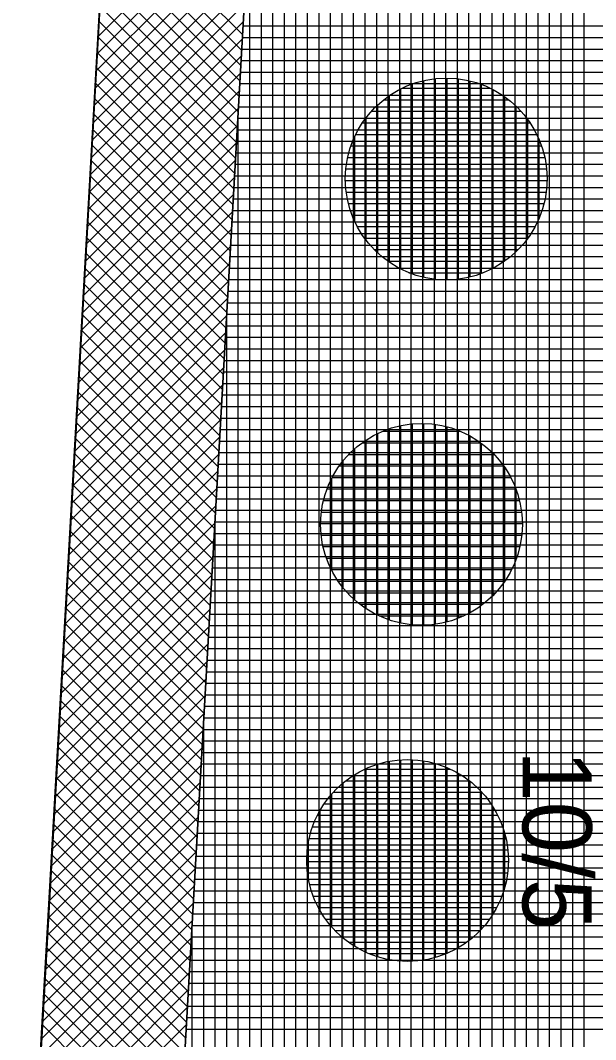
# Model space of a CAD drawing. Extents: x -565346 to -564154, y -1097386 to -1095620.
# Drawn here: x -564266.37 to -564256.39, y -1096598.57 to -1096580.89 of the extents above; entities that cross this region are included whole.
import ezdxf

# ---------------------------------------------------------------- set-up
doc = ezdxf.new("R2010")
doc.units = 0
for name, color, linetype in [('Vrstva 1', 7, 'Continuous'), ('Vrstva 40', 7, 'Continuous'), ('Vrstva 41', 7, 'Continuous'), ('Vrstva 42', 7, 'Continuous'), ('Vrstva 43', 7, 'Continuous'), ('Vrstva 44', 7, 'Continuous')]:
    doc.layers.add(name, color=color, linetype=linetype)

msp = doc.modelspace()

# ---------------------------------------------------------------- linework, layer by layer
at = {"layer": 'Vrstva 1'}
msp.add_line((-564275.31, -1096762.41), (-564264.72, -1096575.85), dxfattribs=at)
at = {"layer": 'Vrstva 41'}
msp.add_lwpolyline([(-564230.6, -1096442.93), (-564234.67, -1096447.65), (-564259.14, -1096527.84), (-564264.72, -1096575.85), (-564272.07, -1096706.16), (-564269.623, -1096706.334), (-564262.228, -1096576.061), (-564256.683, -1096528.354)], close=True, dxfattribs=at)
at = {"layer": 'Vrstva 42'}
for p, q in [((-564262.367, -1096578.518), (-564265.02, -1096581.171)), ((-564264.885, -1096578.772), (-564262.516, -1096581.141)), ((-564262.385, -1096578.818), (-564265.037, -1096581.471)), ((-564262.402, -1096579.118), (-564265.054, -1096581.77)), ((-564264.9, -1096579.04), (-564262.532, -1096581.408)), ((-564264.915, -1096579.308), (-564262.547, -1096581.676)), ((-564262.419, -1096579.418), (-564265.071, -1096582.07)), ((-564264.93, -1096579.575), (-564262.562, -1096581.944)), ((-564262.436, -1096579.718), (-564265.088, -1096582.37)), ((-564264.945, -1096579.843), (-564262.577, -1096582.211)), ((-564262.453, -1096580.018), (-564265.105, -1096582.67)), ((-564264.96, -1096580.111), (-564262.592, -1096582.479)), ((-564262.47, -1096580.317), (-564265.122, -1096582.969)), ((-564264.975, -1096580.379), (-564262.608, -1096582.747)), ((-564262.487, -1096580.617), (-564265.138, -1096583.269)), ((-564264.991, -1096580.646), (-564262.623, -1096583.014)), ((-564262.504, -1096580.917), (-564265.155, -1096583.569)), ((-564265.006, -1096580.914), (-564262.638, -1096583.282)), ((-564262.521, -1096581.217), (-564265.172, -1096583.869)), ((-564265.021, -1096581.182), (-564262.653, -1096583.549)), ((-564262.538, -1096581.517), (-564265.189, -1096584.168)), ((-564265.036, -1096581.45), (-564262.668, -1096583.817)), ((-564265.051, -1096581.717), (-564262.683, -1096584.085)), ((-564262.555, -1096581.817), (-564265.206, -1096584.468)), ((-564262.572, -1096582.117), (-564265.223, -1096584.768)), ((-564265.066, -1096581.985), (-564262.699, -1096584.352)), ((-564265.081, -1096582.253), (-564262.714, -1096584.62)), ((-564262.589, -1096582.417), (-564265.24, -1096585.068)), ((-564265.096, -1096582.521), (-564262.729, -1096584.888)), ((-564262.606, -1096582.716), (-564265.257, -1096585.367)), ((-564265.111, -1096582.788), (-564262.744, -1096585.155)), ((-564262.623, -1096583.016), (-564265.274, -1096585.667)), ((-564265.126, -1096583.056), (-564262.759, -1096585.423)), ((-564262.64, -1096583.316), (-564265.291, -1096585.967)), ((-564265.142, -1096583.324), (-564262.775, -1096585.691)), ((-564262.657, -1096583.616), (-564265.308, -1096586.267)), ((-564265.157, -1096583.591), (-564262.79, -1096585.958)), ((-564265.172, -1096583.859), (-564262.805, -1096586.226)), ((-564262.674, -1096583.916), (-564265.324, -1096586.566)), ((-564262.691, -1096584.216), (-564265.341, -1096586.866)), ((-564265.187, -1096584.127), (-564262.82, -1096586.494)), ((-564265.202, -1096584.395), (-564262.835, -1096586.761)), ((-564262.708, -1096584.516), (-564265.358, -1096587.166)), ((-564265.217, -1096584.662), (-564262.851, -1096587.029)), ((-564262.725, -1096584.815), (-564265.375, -1096587.466)), ((-564265.232, -1096584.93), (-564262.866, -1096587.297)), ((-564262.742, -1096585.115), (-564265.392, -1096587.765)), ((-564265.247, -1096585.198), (-564262.881, -1096587.564)), ((-564262.759, -1096585.415), (-564265.409, -1096588.065)), ((-564265.262, -1096585.466), (-564262.896, -1096587.832)), ((-564262.776, -1096585.715), (-564265.426, -1096588.365)), ((-564265.277, -1096585.733), (-564262.911, -1096588.1)), ((-564262.793, -1096586.015), (-564265.443, -1096588.665)), ((-564265.293, -1096586.001), (-564262.927, -1096588.367)), ((-564262.81, -1096586.315), (-564265.46, -1096588.964)), ((-564265.308, -1096586.269), (-564262.942, -1096588.635)), ((-564265.323, -1096586.537), (-564262.957, -1096588.902)), ((-564262.827, -1096586.615), (-564265.477, -1096589.264)), ((-564262.844, -1096586.914), (-564265.494, -1096589.564)), ((-564265.338, -1096586.804), (-564262.972, -1096589.17)), ((-564265.353, -1096587.072), (-564262.987, -1096589.438)), ((-564262.861, -1096587.214), (-564265.51, -1096589.864)), ((-564265.368, -1096587.34), (-564263.003, -1096589.705)), ((-564262.878, -1096587.514), (-564265.527, -1096590.163)), ((-564265.383, -1096587.608), (-564263.018, -1096589.973)), ((-564262.895, -1096587.814), (-564265.544, -1096590.463)), ((-564265.398, -1096587.875), (-564263.033, -1096590.241)), ((-564262.912, -1096588.114), (-564265.561, -1096590.763)), ((-564265.413, -1096588.143), (-564263.048, -1096590.508)), ((-564262.929, -1096588.414), (-564265.578, -1096591.063)), ((-564265.428, -1096588.411), (-564263.063, -1096590.776)), ((-564265.444, -1096588.679), (-564263.078, -1096591.044)), ((-564262.946, -1096588.714), (-564265.595, -1096591.362)), ((-564262.963, -1096589.014), (-564265.612, -1096591.662)), ((-564265.459, -1096588.946), (-564263.094, -1096591.311)), ((-564265.474, -1096589.214), (-564263.109, -1096591.579)), ((-564262.98, -1096589.313), (-564265.629, -1096591.962)), ((-564265.489, -1096589.482), (-564263.124, -1096591.847)), ((-564262.997, -1096589.613), (-564265.646, -1096592.262)), ((-564263.014, -1096589.913), (-564265.663, -1096592.561)), ((-564265.504, -1096589.75), (-564263.139, -1096592.114)), ((-564265.519, -1096590.017), (-564263.154, -1096592.382)), ((-564263.031, -1096590.213), (-564265.679, -1096592.861)), ((-564265.534, -1096590.285), (-564263.17, -1096592.65)), ((-564263.048, -1096590.513), (-564265.696, -1096593.161)), ((-564265.549, -1096590.553), (-564263.185, -1096592.917)), ((-564263.065, -1096590.813), (-564265.713, -1096593.461)), ((-564265.564, -1096590.82), (-564263.2, -1096593.185)), ((-564263.082, -1096591.113), (-564265.73, -1096593.76)), ((-564265.579, -1096591.088), (-564263.215, -1096593.453)), ((-564263.099, -1096591.412), (-564265.747, -1096594.06)), ((-564265.595, -1096591.356), (-564263.23, -1096593.72)), ((-564265.61, -1096591.624), (-564263.246, -1096593.988)), ((-564263.116, -1096591.712), (-564265.764, -1096594.36)), ((-564263.133, -1096592.012), (-564265.781, -1096594.66)), ((-564265.625, -1096591.891), (-564263.261, -1096594.255)), ((-564265.64, -1096592.159), (-564263.276, -1096594.523)), ((-564263.15, -1096592.312), (-564265.798, -1096594.959)), ((-564265.655, -1096592.427), (-564263.291, -1096594.791)), ((-564263.168, -1096592.612), (-564265.815, -1096595.259)), ((-564265.67, -1096592.695), (-564263.306, -1096595.058)), ((-564263.185, -1096592.912), (-564265.832, -1096595.559)), ((-564265.685, -1096592.962), (-564263.322, -1096595.326)), ((-564263.202, -1096593.212), (-564265.849, -1096595.859)), ((-564265.7, -1096593.23), (-564263.337, -1096595.594)), ((-564263.219, -1096593.511), (-564265.865, -1096596.158)), ((-564265.715, -1096593.498), (-564263.352, -1096595.861)), ((-564265.731, -1096593.766), (-564263.367, -1096596.129)), ((-564263.236, -1096593.811), (-564265.882, -1096596.458)), ((-564263.253, -1096594.111), (-564265.899, -1096596.758)), ((-564265.746, -1096594.033), (-564263.382, -1096596.397)), ((-564265.761, -1096594.301), (-564263.398, -1096596.664)), ((-564263.27, -1096594.411), (-564265.916, -1096597.058)), ((-564265.776, -1096594.569), (-564263.413, -1096596.932)), ((-564263.287, -1096594.711), (-564265.933, -1096597.357)), ((-564265.791, -1096594.837), (-564263.428, -1096597.2)), ((-564263.304, -1096595.011), (-564265.95, -1096597.657)), ((-564265.806, -1096595.104), (-564263.443, -1096597.467)), ((-564263.321, -1096595.311), (-564265.967, -1096597.957)), ((-564265.821, -1096595.372), (-564263.458, -1096597.735)), ((-564263.338, -1096595.611), (-564265.984, -1096598.257)), ((-564265.836, -1096595.64), (-564263.474, -1096598.003)), ((-564263.355, -1096595.91), (-564266.001, -1096598.556)), ((-564265.851, -1096595.908), (-564263.489, -1096598.27)), ((-564263.372, -1096596.21), (-564266.018, -1096598.856)), ((-564265.866, -1096596.175), (-564263.504, -1096598.538)), ((-564265.882, -1096596.443), (-564263.519, -1096598.805)), ((-564263.389, -1096596.51), (-564266.035, -1096599.156)), ((-564263.406, -1096596.81), (-564266.051, -1096599.456)), ((-564265.897, -1096596.711), (-564263.534, -1096599.073)), ((-564265.912, -1096596.979), (-564263.549, -1096599.341)), ((-564263.423, -1096597.11), (-564266.068, -1096599.755)), ((-564265.927, -1096597.246), (-564263.565, -1096599.608)), ((-564263.44, -1096597.41), (-564266.085, -1096600.055)), ((-564265.942, -1096597.514), (-564263.58, -1096599.876)), ((-564263.457, -1096597.71), (-564266.102, -1096600.355)), ((-564265.957, -1096597.782), (-564263.595, -1096600.144)), ((-564263.474, -1096598.009), (-564266.119, -1096600.655)), ((-564265.972, -1096598.05), (-564263.61, -1096600.411)), ((-564263.491, -1096598.309), (-564266.136, -1096600.954)), ((-564265.987, -1096598.317), (-564263.625, -1096600.679))]:
    msp.add_line(p, q, dxfattribs=at)
at = {"layer": 'Vrstva 43'}
for p, q in [((-564256.59, -1096609.053), (-564256.59, -1096528.049)), ((-564256.79, -1096612.576), (-564256.79, -1096529.275)), ((-564256.99, -1096616.099), (-564256.99, -1096530.995)), ((-564257.19, -1096619.622), (-564257.19, -1096532.716)), ((-564257.39, -1096623.145), (-564257.39, -1096534.437)), ((-564257.59, -1096626.667), (-564257.59, -1096536.157)), ((-564257.79, -1096630.19), (-564257.79, -1096537.878)), ((-564257.99, -1096633.713), (-564257.99, -1096539.599)), ((-564258.19, -1096637.236), (-564258.19, -1096541.32)), ((-564258.39, -1096640.759), (-564258.39, -1096543.04)), ((-564258.59, -1096644.281), (-564258.59, -1096544.761)), ((-564258.79, -1096647.804), (-564258.79, -1096546.482)), ((-564258.99, -1096651.327), (-564258.99, -1096548.203)), ((-564259.19, -1096654.85), (-564259.19, -1096549.923)), ((-564259.39, -1096658.372), (-564259.39, -1096551.644)), ((-564259.59, -1096661.895), (-564259.59, -1096553.365)), ((-564259.79, -1096665.418), (-564259.79, -1096555.085)), ((-564259.99, -1096668.941), (-564259.99, -1096556.806)), ((-564260.19, -1096672.464), (-564260.19, -1096558.527)), ((-564260.39, -1096675.986), (-564260.39, -1096560.248)), ((-564260.59, -1096679.509), (-564260.59, -1096561.968)), ((-564260.79, -1096683.032), (-564260.79, -1096563.689)), ((-564260.99, -1096686.555), (-564260.99, -1096565.41)), ((-564261.19, -1096690.078), (-564261.19, -1096567.13)), ((-564261.39, -1096693.6), (-564261.39, -1096568.851)), ((-564261.59, -1096697.123), (-564261.59, -1096570.572)), ((-564261.79, -1096700.646), (-564261.79, -1096572.293)), ((-564261.99, -1096704.169), (-564261.99, -1096574.013)), ((-564262.19, -1096726.788), (-564262.19, -1096575.734)), ((-564262.39, -1096726.776), (-564262.39, -1096578.915)), ((-564262.508, -1096580.99), (-564254.997, -1096580.99)), ((-564262.519, -1096581.19), (-564255.008, -1096581.19)), ((-564262.531, -1096581.39), (-564255.019, -1096581.39)), ((-564262.542, -1096581.59), (-564255.031, -1096581.59)), ((-564262.553, -1096581.79), (-564255.042, -1096581.79)), ((-564262.565, -1096581.99), (-564255.054, -1096581.99)), ((-564262.576, -1096582.19), (-564255.065, -1096582.19)), ((-564262.59, -1096726.765), (-564262.59, -1096582.438)), ((-564262.587, -1096582.39), (-564255.076, -1096582.39)), ((-564262.599, -1096582.59), (-564255.088, -1096582.59)), ((-564262.61, -1096582.79), (-564255.099, -1096582.79)), ((-564262.621, -1096582.99), (-564255.11, -1096582.99)), ((-564262.633, -1096583.19), (-564255.122, -1096583.19)), ((-564262.644, -1096583.39), (-564255.133, -1096583.39)), ((-564262.655, -1096583.59), (-564255.144, -1096583.59)), ((-564262.667, -1096583.79), (-564255.156, -1096583.79)), ((-564262.678, -1096583.99), (-564255.167, -1096583.99)), ((-564262.689, -1096584.19), (-564255.178, -1096584.19)), ((-564262.701, -1096584.39), (-564255.19, -1096584.39)), ((-564262.712, -1096584.59), (-564255.201, -1096584.59)), ((-564262.724, -1096584.79), (-564255.212, -1096584.79)), ((-564262.735, -1096584.99), (-564255.224, -1096584.99)), ((-564262.746, -1096585.19), (-564255.235, -1096585.19)), ((-564262.758, -1096585.39), (-564255.247, -1096585.39)), ((-564262.769, -1096585.59), (-564255.258, -1096585.59)), ((-564262.78, -1096585.79), (-564255.269, -1096585.79)), ((-564262.792, -1096585.99), (-564255.281, -1096585.99)), ((-564262.79, -1096726.753), (-564262.79, -1096585.961)), ((-564262.803, -1096586.19), (-564255.292, -1096586.19)), ((-564262.814, -1096586.39), (-564255.303, -1096586.39)), ((-564262.826, -1096586.59), (-564255.315, -1096586.59)), ((-564262.837, -1096586.79), (-564255.326, -1096586.79)), ((-564262.848, -1096586.99), (-564255.337, -1096586.99)), ((-564262.86, -1096587.19), (-564255.349, -1096587.19)), ((-564262.871, -1096587.39), (-564255.36, -1096587.39)), ((-564262.882, -1096587.59), (-564255.371, -1096587.59)), ((-564262.894, -1096587.79), (-564255.383, -1096587.79)), ((-564262.905, -1096587.99), (-564255.394, -1096587.99)), ((-564262.917, -1096588.19), (-564255.406, -1096588.19)), ((-564262.928, -1096588.39), (-564255.417, -1096588.39)), ((-564262.939, -1096588.59), (-564255.428, -1096588.59)), ((-564262.951, -1096588.79), (-564255.44, -1096588.79)), ((-564262.962, -1096588.99), (-564255.451, -1096588.99)), ((-564262.973, -1096589.19), (-564255.462, -1096589.19)), ((-564262.985, -1096589.39), (-564255.474, -1096589.39)), ((-564262.99, -1096726.742), (-564262.99, -1096589.485)), ((-564262.996, -1096589.59), (-564255.485, -1096589.59)), ((-564263.007, -1096589.79), (-564255.496, -1096589.79)), ((-564263.019, -1096589.99), (-564255.508, -1096589.99)), ((-564263.03, -1096590.19), (-564255.519, -1096590.19)), ((-564263.041, -1096590.39), (-564255.53, -1096590.39)), ((-564263.053, -1096590.59), (-564255.542, -1096590.59)), ((-564263.064, -1096590.79), (-564255.553, -1096590.79)), ((-564263.075, -1096590.99), (-564255.564, -1096590.99)), ((-564263.087, -1096591.19), (-564255.576, -1096591.19)), ((-564263.098, -1096591.39), (-564255.587, -1096591.39)), ((-564263.11, -1096591.59), (-564255.599, -1096591.59)), ((-564263.121, -1096591.79), (-564255.61, -1096591.79)), ((-564263.132, -1096591.99), (-564255.621, -1096591.99)), ((-564263.144, -1096592.19), (-564255.633, -1096592.19)), ((-564263.155, -1096592.39), (-564255.644, -1096592.39)), ((-564263.166, -1096592.59), (-564255.655, -1096592.59)), ((-564263.178, -1096592.79), (-564255.667, -1096592.79)), ((-564263.19, -1096726.731), (-564263.19, -1096593.008)), ((-564263.189, -1096592.99), (-564255.678, -1096592.99)), ((-564263.2, -1096593.19), (-564255.689, -1096593.19)), ((-564263.212, -1096593.39), (-564255.701, -1096593.39)), ((-564263.223, -1096593.59), (-564255.712, -1096593.59)), ((-564263.234, -1096593.79), (-564255.723, -1096593.79)), ((-564263.246, -1096593.99), (-564255.735, -1096593.99)), ((-564263.257, -1096594.19), (-564255.746, -1096594.19)), ((-564263.268, -1096594.39), (-564255.758, -1096594.39)), ((-564263.28, -1096594.59), (-564255.769, -1096594.59)), ((-564263.291, -1096594.79), (-564255.78, -1096594.79)), ((-564263.303, -1096594.99), (-564255.792, -1096594.99)), ((-564263.314, -1096595.19), (-564255.803, -1096595.19)), ((-564263.325, -1096595.39), (-564255.814, -1096595.39)), ((-564263.337, -1096595.59), (-564255.826, -1096595.59)), ((-564263.348, -1096595.79), (-564255.837, -1096595.79)), ((-564263.359, -1096595.99), (-564255.848, -1096595.99)), ((-564263.371, -1096596.19), (-564255.86, -1096596.19)), ((-564263.382, -1096596.39), (-564255.871, -1096596.39)), ((-564263.393, -1096596.59), (-564255.882, -1096596.59)), ((-564263.39, -1096728.822), (-564263.39, -1096596.531)), ((-564263.405, -1096596.79), (-564255.894, -1096596.79)), ((-564263.416, -1096596.99), (-564255.905, -1096596.99)), ((-564263.427, -1096597.19), (-564255.916, -1096597.19)), ((-564263.439, -1096597.39), (-564255.928, -1096597.39)), ((-564263.45, -1096597.59), (-564255.939, -1096597.59)), ((-564263.461, -1096597.79), (-564255.951, -1096597.79)), ((-564263.473, -1096597.99), (-564255.962, -1096597.99)), ((-564263.484, -1096598.19), (-564255.973, -1096598.19)), ((-564263.496, -1096598.39), (-564255.985, -1096598.39))]:
    msp.add_line(p, q, dxfattribs=at)
msp.add_lwpolyline([(-564261.274, -1096726.84), (-564260.141, -1096706.872), (-564262.137, -1096706.758), (-564254.757, -1096576.767), (-564249.271, -1096529.938), (-564240.675, -1096505.018), (-564228.215, -1096460.758), (-564223.301, -1096445.676), (-564221.399, -1096446.296), (-564218.92, -1096438.69), (-564229.82, -1096442.05), (-564230.6, -1096442.93), (-564256.683, -1096528.354), (-564262.228, -1096576.061), (-564269.623, -1096706.334), (-564272.07, -1096706.16), (-564273.28, -1096725.96)], dxfattribs=at)
at = {"layer": 'Vrstva 44'}
for p, q in [((-564259.37, -1096585.351), (-564259.37, -1096581.939)), ((-564259.17, -1096585.383), (-564259.17, -1096581.905)), ((-564258.97, -1096585.392), (-564258.97, -1096581.895)), ((-564258.77, -1096585.379), (-564258.77, -1096581.908)), ((-564258.57, -1096585.343), (-564258.57, -1096581.946)), ((-564259.77, -1096585.207), (-564259.77, -1096582.081)), ((-564259.747, -1096582.07), (-564258.224, -1096582.07)), ((-564259.57, -1096585.291), (-564259.57, -1096581.997)), ((-564258.37, -1096585.282), (-564258.37, -1096582.007)), ((-564258.17, -1096585.191), (-564258.17, -1096582.096)), ((-564260.067, -1096582.27), (-564257.902, -1096582.27)), ((-564259.97, -1096585.088), (-564259.97, -1096582.2)), ((-564257.97, -1096585.068), (-564257.97, -1096582.22)), ((-564260.281, -1096582.47), (-564257.689, -1096582.47)), ((-564260.17, -1096584.929), (-564260.17, -1096582.358)), ((-564257.77, -1096584.902), (-564257.77, -1096582.385)), ((-564260.436, -1096582.67), (-564257.531, -1096582.67)), ((-564260.37, -1096584.709), (-564260.37, -1096582.578)), ((-564257.57, -1096584.673), (-564257.57, -1096582.616)), ((-564260.57, -1096584.382), (-564260.57, -1096582.904)), ((-564260.552, -1096582.87), (-564257.417, -1096582.87)), ((-564257.37, -1096584.315), (-564257.37, -1096582.971)), ((-564260.637, -1096583.07), (-564257.332, -1096583.07)), ((-564260.692, -1096583.27), (-564257.275, -1096583.27)), ((-564260.724, -1096583.47), (-564257.244, -1096583.47)), ((-564260.732, -1096583.67), (-564257.236, -1096583.67)), ((-564260.719, -1096583.87), (-564257.251, -1096583.87)), ((-564260.681, -1096584.07), (-564257.288, -1096584.07)), ((-564260.616, -1096584.27), (-564257.351, -1096584.27)), ((-564260.525, -1096584.47), (-564257.444, -1096584.47)), ((-564260.401, -1096584.67), (-564257.568, -1096584.67)), ((-564260.231, -1096584.87), (-564257.738, -1096584.87)), ((-564259.995, -1096585.07), (-564257.972, -1096585.07)), ((-564259.63, -1096585.27), (-564258.341, -1096585.27)), ((-564259.97, -1096591.291), (-564259.97, -1096587.977)), ((-564259.77, -1096591.346), (-564259.77, -1096587.922)), ((-564259.57, -1096591.375), (-564259.57, -1096587.892)), ((-564259.37, -1096591.381), (-564259.37, -1096587.885)), ((-564259.17, -1096591.365), (-564259.17, -1096587.903)), ((-564258.97, -1096591.327), (-564258.97, -1096587.943)), ((-564260.17, -1096591.21), (-564260.17, -1096588.057)), ((-564260.086, -1096588.02), (-564258.738, -1096588.02)), ((-564258.77, -1096591.26), (-564258.77, -1096588.008)), ((-564258.57, -1096591.165), (-564258.57, -1096588.102)), ((-564260.57, -1096590.945), (-564260.57, -1096588.322)), ((-564260.443, -1096588.22), (-564258.386, -1096588.22)), ((-564260.37, -1096591.1), (-564260.37, -1096588.17)), ((-564258.37, -1096591.038), (-564258.37, -1096588.232)), ((-564260.672, -1096588.42), (-564258.156, -1096588.42)), ((-564258.17, -1096590.862), (-564258.17, -1096588.405)), ((-564260.84, -1096588.62), (-564257.989, -1096588.62)), ((-564260.77, -1096590.738), (-564260.77, -1096588.531)), ((-564257.97, -1096590.619), (-564257.97, -1096588.646)), ((-564260.97, -1096590.431), (-564260.97, -1096588.837)), ((-564260.961, -1096588.82), (-564257.867, -1096588.82)), ((-564261.052, -1096589.02), (-564257.778, -1096589.02)), ((-564257.77, -1096590.232), (-564257.77, -1096589.04)), ((-564261.114, -1096589.22), (-564257.715, -1096589.22)), ((-564261.149, -1096589.42), (-564257.677, -1096589.42)), ((-564261.162, -1096589.62), (-564257.665, -1096589.62)), ((-564261.153, -1096589.82), (-564257.676, -1096589.82)), ((-564261.12, -1096590.02), (-564257.709, -1096590.02)), ((-564261.062, -1096590.22), (-564257.766, -1096590.22)), ((-564260.976, -1096590.42), (-564257.852, -1096590.42)), ((-564260.859, -1096590.62), (-564257.971, -1096590.62)), ((-564260.698, -1096590.82), (-564258.128, -1096590.82)), ((-564260.481, -1096591.02), (-564258.347, -1096591.02)), ((-564260.149, -1096591.22), (-564258.677, -1096591.22)), ((-564260.17, -1096597.135), (-564260.17, -1096593.793)), ((-564259.97, -1096597.183), (-564259.97, -1096593.743)), ((-564259.77, -1096597.208), (-564259.77, -1096593.719)), ((-564259.57, -1096597.211), (-564259.57, -1096593.718)), ((-564259.37, -1096597.191), (-564259.37, -1096593.739)), ((-564259.17, -1096597.144), (-564259.17, -1096593.784)), ((-564260.57, -1096596.954), (-564260.57, -1096593.974)), ((-564260.394, -1096593.88), (-564258.915, -1096593.88)), ((-564260.37, -1096597.059), (-564260.37, -1096593.869)), ((-564258.97, -1096597.073), (-564258.97, -1096593.854)), ((-564258.77, -1096596.973), (-564258.77, -1096593.956)), ((-564260.77, -1096596.81), (-564260.77, -1096594.118)), ((-564260.725, -1096594.08), (-564258.586, -1096594.08)), ((-564258.57, -1096596.836), (-564258.57, -1096594.092)), ((-564260.97, -1096596.617), (-564260.97, -1096594.311)), ((-564260.941, -1096594.28), (-564258.368, -1096594.28)), ((-564258.37, -1096596.652), (-564258.37, -1096594.278)), ((-564261.099, -1096594.48), (-564258.207, -1096594.48)), ((-564261.217, -1096594.68), (-564258.092, -1096594.68)), ((-564261.17, -1096596.338), (-564261.17, -1096594.591)), ((-564258.17, -1096596.39), (-564258.17, -1096594.541)), ((-564261.304, -1096594.88), (-564258.006, -1096594.88)), ((-564257.97, -1096595.936), (-564257.97, -1096594.996)), ((-564261.37, -1096595.798), (-564261.37, -1096595.13)), ((-564261.36, -1096595.08), (-564257.947, -1096595.08)), ((-564261.392, -1096595.28), (-564257.915, -1096595.28)), ((-564261.402, -1096595.48), (-564257.906, -1096595.48)), ((-564261.39, -1096595.68), (-564257.92, -1096595.68)), ((-564261.353, -1096595.88), (-564257.956, -1096595.88)), ((-564261.29, -1096596.08), (-564258.017, -1096596.08)), ((-564261.2, -1096596.28), (-564258.108, -1096596.28)), ((-564261.079, -1096596.48), (-564258.231, -1096596.48)), ((-564260.91, -1096596.68), (-564258.398, -1096596.68)), ((-564260.679, -1096596.88), (-564258.628, -1096596.88)), ((-564260.324, -1096597.08), (-564258.988, -1096597.08))]:
    msp.add_line(p, q, dxfattribs=at)
for centre in [(-564258.984, -1096583.644), (-564259.414, -1096589.634), (-564259.654, -1096595.464)]:
    msp.add_circle(centre, 1.75, dxfattribs=at)

# ---------------------------------------------------------------- texts
at = {"layer": 'Vrstva 40'}
msp.add_text('10/5', height=1.2, rotation=270, dxfattribs=at).set_placement((-564257.66, -1096593.55))

doc.saveas('drawing.dxf')
